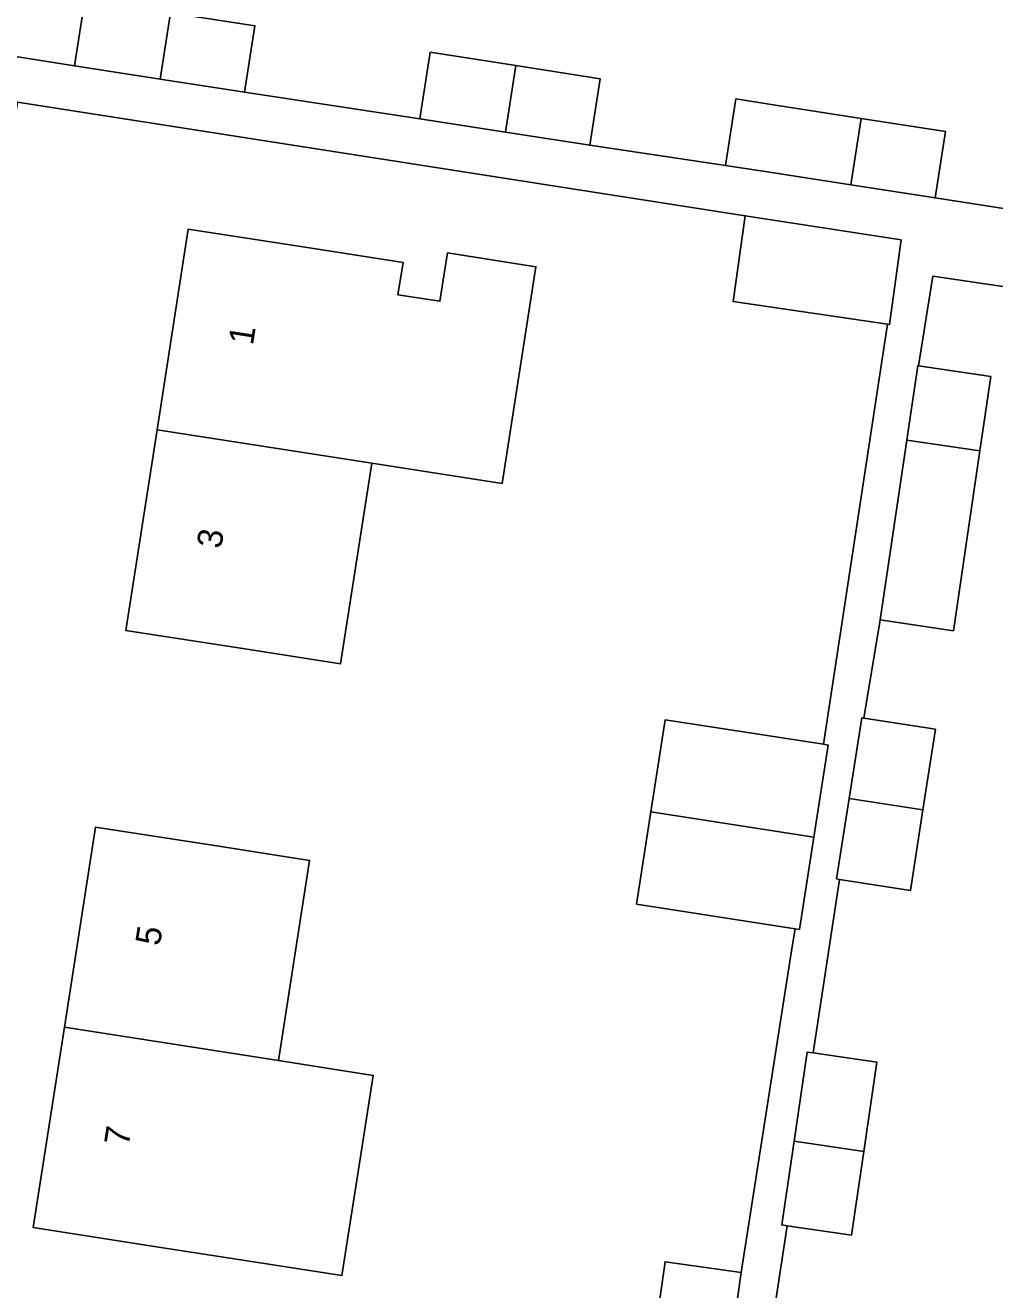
# Model space of a CAD drawing. Extents: x 161483 to 162250, y 379484 to 380833.
# Drawn here: x 162098.1 to 162137, y 380433 to 380483.7 of the extents above; entities that cross this region are included whole.
import ezdxf

# ---------------------------------------------------------------- set-up
doc = ezdxf.new("R2010")
doc.units = 0
for name, color, linetype in [('IMGEO_Erf', 7, 'Continuous'), ('IMGEO_Pand', 7, 'Continuous'), ('IMGEO_Pand_nummerreeks', 7, 'Continuous'), ('IMGEO_Voetpad_open', 7, 'Continuous')]:
    doc.layers.add(name, color=color, linetype=linetype)

msp = doc.modelspace()

# ---------------------------------------------------------------- linework, layer by layer
at = {"layer": 'IMGEO_Erf'}
for points in [[(162094.186, 380500), (162091.547, 380483.388), (162100.085, 380482.032), (162100.5, 380484.696)], [(162103.933, 380484.162), (162107.309, 380483.637), (162106.895, 380480.972), (162113.923, 380479.911), (162114.338, 380482.575), (162117.771, 380482.041), (162121.147, 380481.516), (162120.733, 380478.851), (162126.172, 380478.044), (162126.587, 380480.708), (162128.178, 380480.461), (162131.611, 380479.927), (162134.987, 380479.402), (162134.573, 380476.737), (162141.597, 380475.653)], [(162123.316, 380431.017), (162123.748, 380434.105), (162126.8, 380433.678), (162128.86, 380446.817), (162128.958, 380447.449), (162122.606, 380448.437), (162123.181, 380452.133), (162123.756, 380455.828), (162130.106, 380454.84), (162132.658, 380471.674), (162126.478, 380472.584), (162126.961, 380476.027), (162097.794, 380480.577), (162097.19, 380476.656), (162093.544, 380477.259), (162096.227, 380470.413), (162094.403, 380458.584), (162093.843, 380454.949), (162090.678, 380434.418), (162090.113, 380430.753)], [(162151.539, 380471.087), (162134.481, 380473.597), (162133.908, 380470.008), (162136.808, 380469.581), (162136.37, 380466.603), (162135.309, 380459.393), (162132.375, 380459.825), (162131.712, 380455.888), (162134.587, 380455.441), (162134.085, 380452.212), (162133.582, 380448.983), (162130.736, 380449.427), (162129.686, 380442.474), (162132.236, 380442.098), (162131.71, 380438.523), (162131.216, 380435.168), (162128.64, 380435.548), (162127.581, 380428.539)]]:
    msp.add_lwpolyline(points, dxfattribs=at)
for points in [[(162102.139, 380459.408), (162103.391, 380467.45), (162104.642, 380475.49), (162109.583, 380474.721), (162113.249, 380474.151), (162113.048, 380472.859), (162114.73, 380472.597), (162115.031, 380474.532), (162118.577, 380473.981), (162117.226, 380465.298), (162111.998, 380466.111), (162110.747, 380458.069), (162107.08, 380458.639)], [(162107.005, 380434.14), (162103.372, 380434.706), (162098.431, 380435.475), (162099.68, 380443.5), (162100.928, 380451.524), (162105.869, 380450.755), (162109.502, 380450.189), (162108.253, 380442.164), (162112.054, 380441.572), (162111.545, 380438.306), (162110.804, 380433.548)]]:
    msp.add_lwpolyline(points, close=True, dxfattribs=at)
at = {"layer": 'IMGEO_Pand'}
for points in [[(162103.52, 380481.497), (162103.933, 380484.162), (162100.5, 380484.696), (162100.085, 380482.032)], [(162103.52, 380481.497), (162106.895, 380480.972), (162107.309, 380483.637), (162103.933, 380484.162)], [(162117.771, 380482.041), (162114.338, 380482.575), (162113.923, 380479.911), (162117.358, 380479.376)], [(162117.771, 380482.041), (162117.358, 380479.376), (162120.733, 380478.851), (162121.147, 380481.516)], [(162131.611, 380479.927), (162128.178, 380480.461), (162126.587, 380480.708), (162126.172, 380478.044), (162127.763, 380477.797), (162131.198, 380477.262)], [(162131.198, 380477.262), (162134.573, 380476.737), (162134.987, 380479.402), (162131.611, 380479.927)], [(162126.961, 380476.027), (162126.478, 380472.584), (162132.658, 380471.674), (162132.749, 380471.66), (162133.211, 380475.056)], [(162113.048, 380472.859), (162113.249, 380474.151), (162109.583, 380474.721), (162104.642, 380475.49), (162103.391, 380467.45), (162111.998, 380466.111), (162117.226, 380465.298), (162118.577, 380473.981), (162115.031, 380474.532), (162114.73, 380472.597)], [(162133.908, 380470.008), (162133.874, 380470.013), (162133.463, 380467.22), (162133.436, 380467.035), (162136.37, 380466.603), (162136.808, 380469.581)], [(162103.391, 380467.45), (162102.139, 380459.408), (162107.08, 380458.639), (162110.747, 380458.069), (162111.998, 380466.111)], [(162136.37, 380466.603), (162133.436, 380467.035), (162132.375, 380459.825), (162135.309, 380459.393)], [(162131.712, 380455.888), (162131.63, 380455.901), (162131.127, 380452.672), (162134.085, 380452.212), (162134.587, 380455.441)], [(162130.106, 380454.84), (162123.756, 380455.828), (162123.181, 380452.133), (162129.718, 380451.115), (162130.293, 380454.811)], [(162134.085, 380452.212), (162131.127, 380452.672), (162130.624, 380449.444), (162130.736, 380449.427), (162133.582, 380448.983)], [(162129.718, 380451.115), (162123.181, 380452.133), (162122.606, 380448.437), (162128.958, 380447.449), (162129.143, 380447.42)], [(162099.68, 380443.5), (162108.253, 380442.164), (162109.502, 380450.189), (162105.869, 380450.755), (162100.928, 380451.524)], [(162112.054, 380441.572), (162108.253, 380442.164), (162099.68, 380443.5), (162098.431, 380435.475), (162103.372, 380434.706), (162107.005, 380434.14), (162110.804, 380433.548), (162111.545, 380438.306)], [(162129.686, 380442.474), (162129.448, 380442.509), (162128.922, 380438.935), (162131.71, 380438.523), (162132.236, 380442.098)], [(162131.71, 380438.523), (162128.922, 380438.935), (162128.428, 380435.579), (162128.64, 380435.548), (162131.216, 380435.168)], [(162125.935, 380427.495), (162126.8, 380433.678), (162123.748, 380434.105), (162123.316, 380431.017), (162119.595, 380431.538), (162119.172, 380428.517)]]:
    msp.add_lwpolyline(points, close=True, dxfattribs=at)
at = {"layer": 'IMGEO_Voetpad_open'}
for points in [[(162141.597, 380475.653), (162134.573, 380476.737), (162131.198, 380477.262), (162127.763, 380477.797), (162126.172, 380478.044), (162120.733, 380478.851), (162117.358, 380479.376), (162113.923, 380479.911), (162106.895, 380480.972), (162103.52, 380481.497), (162100.085, 380482.032), (162091.547, 380483.388)], [(162097.794, 380480.577), (162126.961, 380476.027), (162133.211, 380475.056), (162132.749, 380471.66), (162132.658, 380471.674), (162130.106, 380454.84), (162130.293, 380454.811), (162129.718, 380451.115), (162129.143, 380447.42), (162128.958, 380447.449), (162128.86, 380446.817), (162126.8, 380433.678), (162125.935, 380427.495)], [(162127.581, 380428.539), (162128.64, 380435.548), (162128.428, 380435.579), (162128.922, 380438.935), (162129.448, 380442.509), (162129.686, 380442.474), (162130.736, 380449.427), (162130.624, 380449.444), (162131.127, 380452.672), (162131.63, 380455.901), (162131.712, 380455.888), (162132.375, 380459.825), (162133.436, 380467.035), (162133.463, 380467.22), (162133.874, 380470.013), (162133.908, 380470.008), (162134.481, 380473.597), (162151.539, 380471.087)]]:
    msp.add_lwpolyline(points, dxfattribs=at)

# ---------------------------------------------------------------- texts
at = {"layer": 'IMGEO_Pand_nummerreeks'}
for s, rotation, p in [('1', 81.1537, (162107.233, 380470.807)), ('3', 81.1535, (162105.963, 380462.653)), ('5', 81.1565, (162103.502, 380446.736)), ('7', 81.1537, (162102.254, 380438.711))]:
    msp.add_text(s, height=1, rotation=rotation, dxfattribs=at).set_placement(p)

doc.saveas('drawing.dxf')
